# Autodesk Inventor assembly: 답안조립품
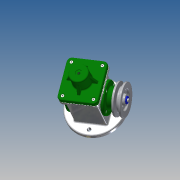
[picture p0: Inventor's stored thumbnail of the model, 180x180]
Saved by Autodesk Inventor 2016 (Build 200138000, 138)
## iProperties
Created: 2018-10
Part Number: 답안조립품
Document SubType Name: Assembly
Designer: Administrator
Author: Administrator
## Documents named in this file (18)
- Y:\481007V1010 배철윤\답안조립품.iam
- Y:\481007V1010 배철윤\본체.ipt
- Y:\481007V1010 배철윤\뒤커버.ipt
- Y:\481007V1010 배철윤\앞커버.ipt
- Y:\481007V1010 배철윤\베어링 17 x 40 x 12.ipt
- Y:\481007V1010 배철윤\오일 실 17 30 8.ipt
- Y:\481007V1010 배철윤\편심축.ipt
- Y:\481007V1010 배철윤\링크.ipt
- Y:\481007V1010 배철윤\키 4 x 4 x 12.ipt
- Y:\481007V1010 배철윤\V-벨트풀리.ipt
- Y:\481007V1010 배철윤\와셔 4x16.ipt
- Y:\481007V1010 배철윤\볼트 M4 x 10.ipt
- Y:\481007V1010 배철윤\클레비스 핀 6 x 22.ipt
- 클레비스 핀 6 x 22.ipt
- Y:\481007V1010 배철윤\E-링.ipt
- Y:\481007V1010 배철윤\슬라이더.ipt
- Y:\481007V1010 배철윤\덮개.ipt
- Y:\481007V1010 배철윤\볼트 M4 x 8.ipt
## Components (2 placed, 2 different names)
1. V-벨트풀리:1
2. E-링:1
